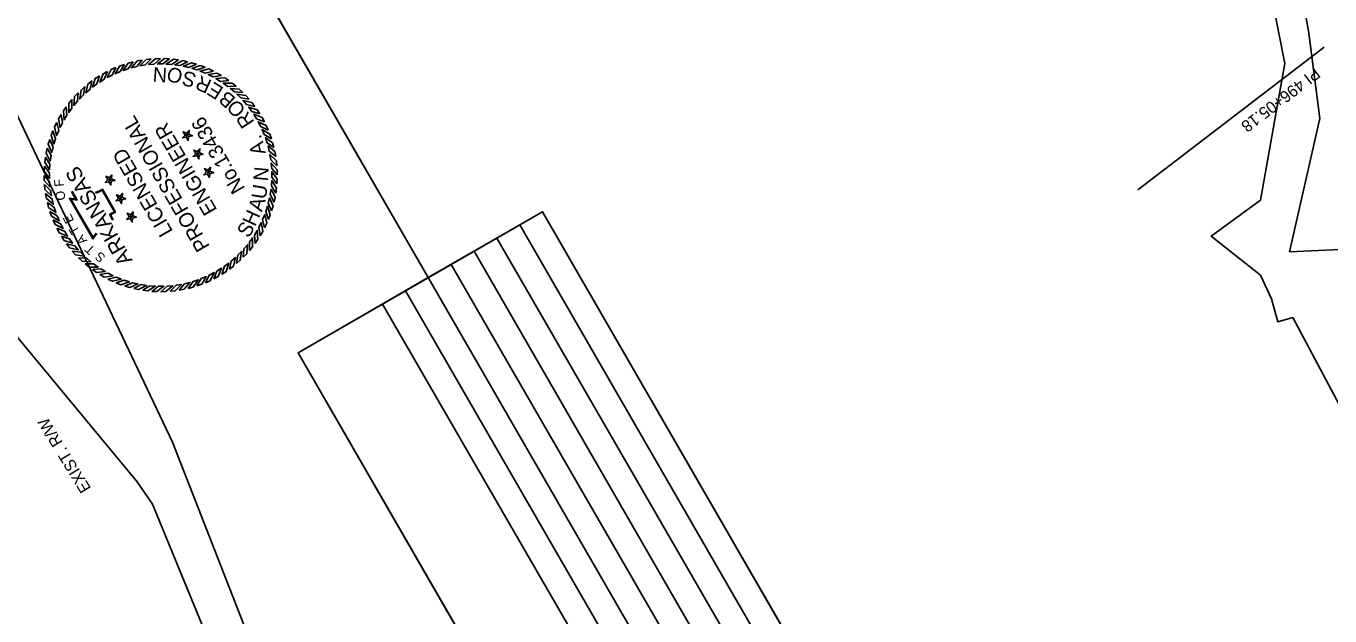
# Model space of a CAD drawing. Extents: x 956270 to 957915, y 1920520 to 1922423.
# Drawn here: x 956611 to 957278, y 1921729 to 1922031 of the extents above; entities that cross this region are included whole.
import ezdxf

# ---------------------------------------------------------------- set-up
doc = ezdxf.new("R2010")
doc.units = 0
for name, color, linetype in [('1', 7, 'Continuous'), ('Default', 7, 'Continuous'), ('G-ANNO-SYMB', 7, 'Continuous'), ('NO PLOT', 7, 'Continuous'), ('R_Draft', 7, 'Continuous'), ('R_Horz Alg Annot', 7, 'Continuous')]:
    doc.layers.add(name, color=color, linetype=linetype)

msp = doc.modelspace()

# ---------------------------------------------------------------- linework, layer by layer
at = {"layer": '1'}
msp.add_line((956816.66, 1921901.98), (956666.17, 1922162.65), dxfattribs=at)
at = {"layer": 'Default'}
for p, q in [((956749.98, 1921863.48), (956875.12, 1921935.73)), ((957087.62, 1921567.67), (956875.12, 1921935.73)), ((957075.93, 1921560.92), (956863.43, 1921928.98)), ((957064.24, 1921554.17), (956851.74, 1921922.23)), ((957052.55, 1921547.42), (956840.05, 1921915.48)), ((957040.85, 1921540.67), (956828.35, 1921908.73)), ((957040.85, 1921540.67), (956828.35, 1921908.73)), ((957029.16, 1921533.92), (956816.66, 1921901.98)), ((957017.47, 1921527.17), (956804.97, 1921895.23)), ((957005.78, 1921520.42), (956793.28, 1921888.48)), ((956962.48, 1921495.42), (956749.98, 1921863.48))]:
    msp.add_line(p, q, dxfattribs=at)
at = {"layer": 'G-ANNO-SYMB'}
for points in [[(956670.21, 1922013.36), (956667.68, 1922012.9), (956664.74, 1922009.4), (956667.43, 1922010.06)], [(956674.86, 1922013.92), (956672.3, 1922013.66), (956669.1, 1922010.4), (956671.83, 1922010.85)], [(956679.54, 1922014.12), (956676.97, 1922014.06), (956673.52, 1922011.06), (956676.28, 1922011.29)], [(956684.22, 1922013.95), (956681.66, 1922014.09), (956677.98, 1922011.37), (956680.75, 1922011.38)], [(956688.87, 1922013.41), (956686.33, 1922013.75), (956682.45, 1922011.32), (956685.21, 1922011.12)], [(956693.47, 1922012.5), (956690.96, 1922013.04), (956686.9, 1922010.93), (956689.64, 1922010.51)], [(956652.47, 1922007.55), (956650.21, 1922006.33), (956648.5, 1922002.09), (956650.85, 1922003.55)], [(956656.72, 1922009.52), (956654.37, 1922008.48), (956652.33, 1922004.39), (956654.79, 1922005.66)], [(956661.11, 1922011.15), (956658.69, 1922010.3), (956656.33, 1922006.38), (956658.89, 1922007.46)], [(956665.61, 1922012.44), (956663.13, 1922011.78), (956660.48, 1922008.06), (956663.11, 1922008.93)], [(956697.98, 1922011.24), (956695.52, 1922011.98), (956691.31, 1922010.19), (956694.01, 1922009.56)], [(956702.38, 1922009.63), (956699.98, 1922010.56), (956695.65, 1922009.11), (956698.29, 1922008.26)], [(956706.64, 1922007.68), (956704.32, 1922008.79), (956699.89, 1922007.68), (956702.45, 1922006.64)], [(956710.73, 1922005.4), (956708.51, 1922006.69), (956704, 1922005.94), (956706.48, 1922004.69)], [(956640.83, 1921999.73), (956638.91, 1921998.02), (956638.24, 1921993.5), (956640.19, 1921995.47)], [(956644.5, 1922002.64), (956642.46, 1922001.08), (956641.43, 1921996.63), (956643.53, 1921998.44)], [(956648.39, 1922005.25), (956646.23, 1922003.86), (956644.86, 1921999.5), (956647.09, 1922001.14)], [(956714.63, 1922002.81), (956712.52, 1922004.27), (956707.96, 1922003.87), (956710.34, 1922002.43)], [(956718.32, 1921999.92), (956716.33, 1922001.54), (956711.75, 1922001.5), (956714, 1921999.88)], [(956634.22, 1921993.1), (956632.6, 1921991.11), (956632.64, 1921986.53), (956634.26, 1921988.78)], [(956637.39, 1921996.54), (956635.62, 1921994.69), (956635.3, 1921990.12), (956637.09, 1921992.24)], [(956721.76, 1921996.75), (956719.91, 1921998.52), (956715.35, 1921998.84), (956717.46, 1921997.05)], [(956724.95, 1921993.31), (956723.24, 1921995.22), (956718.72, 1921995.9), (956720.69, 1921993.95)], [(956727.86, 1921989.64), (956726.3, 1921991.68), (956721.85, 1921992.71), (956723.66, 1921990.61)], [(956631.33, 1921989.41), (956629.87, 1921987.3), (956630.27, 1921982.74), (956631.71, 1921985.11)], [(956730.47, 1921985.75), (956729.08, 1921987.91), (956724.72, 1921989.28), (956726.36, 1921987.05)], [(956626.46, 1921981.42), (956625.35, 1921979.1), (956626.45, 1921974.67), (956627.5, 1921977.23)], [(956628.74, 1921985.51), (956627.45, 1921983.29), (956628.2, 1921978.78), (956629.45, 1921981.26)], [(956732.77, 1921981.67), (956731.55, 1921983.93), (956727.31, 1921985.64), (956728.77, 1921983.29)], [(956734.74, 1921977.42), (956733.7, 1921979.77), (956729.61, 1921981.81), (956730.88, 1921979.35)], [(956622.9, 1921972.76), (956622.16, 1921970.3), (956623.95, 1921966.09), (956624.58, 1921968.79)], [(956624.51, 1921977.16), (956623.58, 1921974.76), (956625.03, 1921970.43), (956625.87, 1921973.07)], [(956693.21, 1921974.87), (956692.18, 1921974.98), (956690.85, 1921973.51), (956692.79, 1921973.92)], [(956693.21, 1921974.87), (956693, 1921975.89), (956691.19, 1921976.69), (956692.18, 1921974.98)], [(956693.21, 1921974.87), (956692.79, 1921973.92), (956693.78, 1921972.2), (956693.99, 1921974.17)], [(956693.21, 1921974.87), (956694.12, 1921975.39), (956694.32, 1921977.36), (956693, 1921975.89)], [(956693.21, 1921974.87), (956693.99, 1921974.17), (956695.93, 1921974.58), (956694.12, 1921975.39)], [(956736.37, 1921973.03), (956735.52, 1921975.45), (956731.6, 1921977.81), (956732.68, 1921975.25)], [(956737.66, 1921968.53), (956737, 1921971.01), (956733.28, 1921973.66), (956734.15, 1921971.03)], [(956621.64, 1921968.25), (956621.1, 1921965.74), (956623.21, 1921961.68), (956623.63, 1921964.42)], [(956698.67, 1921965.42), (956698.45, 1921966.44), (956696.64, 1921967.25), (956697.63, 1921965.53)], [(956698.67, 1921965.42), (956699.57, 1921965.94), (956699.78, 1921967.91), (956698.45, 1921966.44)], [(956698.67, 1921965.42), (956699.44, 1921964.72), (956701.38, 1921965.14), (956699.57, 1921965.94)], [(956738.58, 1921963.93), (956738.12, 1921966.46), (956734.62, 1921969.4), (956735.28, 1921966.7)], [(956620.73, 1921963.65), (956620.39, 1921961.11), (956622.81, 1921957.23), (956623.02, 1921959.99)], [(956698.67, 1921965.42), (956697.63, 1921965.53), (956696.31, 1921964.06), (956698.24, 1921964.47)], [(956698.67, 1921965.42), (956698.24, 1921964.47), (956699.23, 1921962.75), (956699.44, 1921964.72)], [(956739.14, 1921959.28), (956738.88, 1921961.84), (956735.62, 1921965.04), (956736.07, 1921962.3)], [(956739.34, 1921954.6), (956739.28, 1921957.17), (956736.28, 1921960.62), (956736.51, 1921957.86)], [(956620.02, 1921954.32), (956620.08, 1921951.75), (956623.08, 1921948.3), (956622.85, 1921951.06)], [(956620.19, 1921959), (956620.05, 1921956.44), (956622.77, 1921952.76), (956622.76, 1921955.53)], [(956653.65, 1921952.03), (956653.43, 1921953.05), (956651.62, 1921953.85), (956652.62, 1921952.14)], [(956653.65, 1921952.03), (956654.55, 1921952.55), (956654.76, 1921954.52), (956653.43, 1921953.05)], [(956653.65, 1921952.03), (956654.43, 1921951.33), (956656.36, 1921951.74), (956654.55, 1921952.55)], [(956704.12, 1921955.97), (956703.09, 1921956.08), (956701.76, 1921954.61), (956703.7, 1921955.02)], [(956704.12, 1921955.97), (956703.91, 1921956.99), (956702.1, 1921957.8), (956703.09, 1921956.08)], [(956704.12, 1921955.97), (956703.7, 1921955.02), (956704.69, 1921953.31), (956704.9, 1921955.28)], [(956704.12, 1921955.97), (956705.02, 1921956.5), (956705.23, 1921958.47), (956703.91, 1921956.99)], [(956704.12, 1921955.97), (956704.9, 1921955.28), (956706.83, 1921955.69), (956705.02, 1921956.5)], [(956739.17, 1921949.92), (956739.31, 1921952.48), (956736.59, 1921956.16), (956736.6, 1921953.39)], [(956620.22, 1921949.64), (956620.48, 1921947.08), (956623.74, 1921943.88), (956623.29, 1921946.61)], [(956653.65, 1921952.03), (956652.62, 1921952.14), (956651.29, 1921950.66), (956653.23, 1921951.08)], [(956653.65, 1921952.03), (956653.23, 1921951.08), (956654.22, 1921949.36), (956654.43, 1921951.33)], [(956737.72, 1921940.67), (956738.26, 1921943.18), (956736.15, 1921947.24), (956735.73, 1921944.5)], [(956738.63, 1921945.27), (956738.97, 1921947.81), (956736.54, 1921951.69), (956736.34, 1921948.92)], [(956620.78, 1921944.98), (956621.24, 1921942.46), (956624.74, 1921939.52), (956624.08, 1921942.21)], [(956621.7, 1921940.39), (956622.36, 1921937.91), (956626.08, 1921935.26), (956625.21, 1921937.89)], [(956659.11, 1921942.58), (956658.07, 1921942.69), (956656.74, 1921941.22), (956658.68, 1921941.63)], [(956659.11, 1921942.58), (956658.89, 1921943.6), (956657.08, 1921944.41), (956658.07, 1921942.69)], [(956659.11, 1921942.58), (956658.68, 1921941.63), (956659.67, 1921939.91), (956659.88, 1921941.88)], [(956659.11, 1921942.58), (956660.01, 1921943.1), (956660.22, 1921945.07), (956658.89, 1921943.6)], [(956659.11, 1921942.58), (956659.88, 1921941.88), (956661.82, 1921942.3), (956660.01, 1921943.1)], [(956736.46, 1921936.16), (956737.2, 1921938.62), (956735.41, 1921942.83), (956734.78, 1921940.13)], [(956622.98, 1921935.89), (956623.84, 1921933.47), (956627.76, 1921931.11), (956626.68, 1921933.67)], [(956664.56, 1921933.13), (956663.52, 1921933.24), (956662.2, 1921931.77), (956664.14, 1921932.18)], [(956664.56, 1921933.13), (956664.34, 1921934.15), (956662.53, 1921934.96), (956663.52, 1921933.24)], [(956664.56, 1921933.13), (956664.14, 1921932.18), (956665.13, 1921930.47), (956665.33, 1921932.44)], [(956664.56, 1921933.13), (956665.46, 1921933.65), (956665.67, 1921935.62), (956664.34, 1921934.15)], [(956664.56, 1921933.13), (956665.33, 1921932.44), (956667.27, 1921932.85), (956665.46, 1921933.65)], [(956732.9, 1921927.5), (956734.01, 1921929.82), (956732.91, 1921934.25), (956731.86, 1921931.69)], [(956734.85, 1921931.76), (956735.78, 1921934.15), (956734.33, 1921938.49), (956733.48, 1921935.85)], [(956624.62, 1921931.5), (956625.65, 1921929.15), (956629.75, 1921927.11), (956628.48, 1921929.57)], [(956626.59, 1921927.25), (956627.81, 1921924.99), (956632.05, 1921923.28), (956630.59, 1921925.63)], [(956728.03, 1921919.51), (956729.49, 1921921.62), (956729.09, 1921926.17), (956727.65, 1921923.8)], [(956730.62, 1921923.41), (956731.91, 1921925.63), (956731.16, 1921930.14), (956729.91, 1921927.66)], [(956628.89, 1921923.17), (956630.28, 1921921.01), (956634.64, 1921919.64), (956633, 1921921.87)], [(956631.5, 1921919.28), (956633.06, 1921917.24), (956637.51, 1921916.21), (956635.7, 1921918.31)], [(956725.14, 1921915.82), (956726.76, 1921917.81), (956726.72, 1921922.39), (956725.1, 1921920.13)], [(956634.41, 1921915.6), (956636.12, 1921913.69), (956640.64, 1921913.02), (956638.67, 1921914.97)], [(956718.53, 1921909.19), (956720.44, 1921910.9), (956721.12, 1921915.42), (956719.17, 1921913.45)], [(956721.97, 1921912.38), (956723.74, 1921914.23), (956724.06, 1921918.79), (956722.27, 1921916.68)], [(956637.6, 1921912.17), (956639.45, 1921910.4), (956644.01, 1921910.08), (956641.9, 1921911.87)], [(956641.04, 1921909), (956643.03, 1921907.38), (956647.61, 1921907.42), (956645.35, 1921909.04)], [(956644.73, 1921906.11), (956646.84, 1921904.65), (956651.4, 1921905.05), (956649.02, 1921906.49)], [(956706.89, 1921901.37), (956709.15, 1921902.59), (956710.86, 1921906.83), (956708.51, 1921905.37)], [(956710.97, 1921903.67), (956713.13, 1921905.06), (956714.5, 1921909.42), (956712.27, 1921907.78)], [(956714.86, 1921906.28), (956716.9, 1921907.84), (956717.93, 1921912.29), (956715.83, 1921910.48)], [(956648.63, 1921903.52), (956650.85, 1921902.23), (956655.36, 1921902.98), (956652.88, 1921904.23)], [(956652.72, 1921901.24), (956655.04, 1921900.13), (956659.47, 1921901.23), (956656.91, 1921902.28)], [(956656.98, 1921899.29), (956659.37, 1921898.36), (956663.71, 1921899.81), (956661.07, 1921900.65)], [(956661.38, 1921897.68), (956663.84, 1921896.94), (956668.05, 1921898.73), (956665.35, 1921899.36)], [(956689.15, 1921895.56), (956691.68, 1921896.02), (956694.62, 1921899.52), (956691.93, 1921898.86)], [(956693.75, 1921896.48), (956696.23, 1921897.14), (956698.88, 1921900.86), (956696.25, 1921899.99)], [(956698.25, 1921897.76), (956700.67, 1921898.62), (956703.03, 1921902.53), (956700.47, 1921901.46)], [(956702.64, 1921899.4), (956704.99, 1921900.43), (956707.03, 1921904.53), (956704.57, 1921903.25)], [(956665.89, 1921896.41), (956668.4, 1921895.88), (956672.46, 1921897.99), (956669.72, 1921898.41)], [(956670.49, 1921895.51), (956673.03, 1921895.17), (956676.91, 1921897.59), (956674.14, 1921897.8)], [(956675.14, 1921894.97), (956677.7, 1921894.83), (956681.38, 1921897.55), (956678.61, 1921897.54)], [(956679.82, 1921894.8), (956682.39, 1921894.86), (956685.84, 1921897.86), (956683.08, 1921897.63)], [(956684.5, 1921895), (956687.06, 1921895.26), (956690.26, 1921898.52), (956687.53, 1921898.07)]]:
    msp.add_lwpolyline(points, close=True, dxfattribs=at)
for points in [[(956646.96, 1921924.53), (956645.05, 1921921.82), (956633, 1921942.65), (956636.2, 1921942.18), (956635.36, 1921943.58), (956634.66, 1921944.76), (956634.11, 1921946.01)], [(956646.65, 1921924.75), (956645.08, 1921922.53), (956633.73, 1921942.16), (956636.93, 1921941.68), (956635.69, 1921943.78), (956635, 1921944.93), (956634.46, 1921946.16)], [(956646.12, 1921945.57), (956646.73, 1921945.34), (956647.37, 1921945.51), (956648.57, 1921946.03), (956649.7, 1921946.69), (956656.03, 1921935.71), (956654.42, 1921934.78), (956653.74, 1921934.39), (956653.95, 1921933.5), (956654.83, 1921931.98), (956654.64, 1921931.61)], [(956646.25, 1921945.93), (956646.75, 1921945.74), (956647.25, 1921945.87), (956648.4, 1921946.37), (956649.84, 1921947.21), (956656.55, 1921935.57), (956654.61, 1921934.45), (956654.18, 1921934.2), (956654.3, 1921933.65), (956655.26, 1921931.99), (956654.98, 1921931.44)]]:
    msp.add_lwpolyline(points, dxfattribs=at)
at = {"layer": 'NO PLOT'}
for points in [[(957915.18, 1921041.6), (957117.5, 1922423.23), (956666.17, 1922162.65), (956816.66, 1921901.98), (956875.12, 1921935.73), (957087.62, 1921567.67), (957029.16, 1921533.92), (957172.25, 1921286.08), (957225.74, 1921316.96), (957397.07, 1921020.21), (957343.58, 1920989.33), (957463.85, 1920781.02)], [(957915.18, 1921041.6), (957117.5, 1922423.23), (956666.17, 1922162.65), (956816.66, 1921901.98), (956875.12, 1921935.73), (957087.62, 1921567.67), (957029.16, 1921533.92), (957172.25, 1921286.08), (957225.74, 1921316.96), (957397.07, 1921020.21), (957343.58, 1920989.33), (957463.85, 1920781.02)], [(957915.18, 1921041.6), (957117.5, 1922423.23), (956666.17, 1922162.65), (956816.66, 1921901.98), (956875.12, 1921935.73), (957087.62, 1921567.67), (957029.16, 1921533.92), (957172.25, 1921286.08), (957225.74, 1921316.96), (957397.07, 1921020.21), (957343.58, 1920989.33), (957463.85, 1920781.02)], [(957012.51, 1920520.44), (956420.48, 1921545.87), (956463.26, 1921570.57), (956365.36, 1921740.14), (956378, 1921747.44), (956270.25, 1921934.07), (956666.17, 1922162.65), (956816.66, 1921901.98), (956749.98, 1921863.48), (956962.48, 1921495.42), (957029.16, 1921533.92), (957172.25, 1921286.08), (957120.9, 1921256.43), (957292.23, 1920959.68), (957343.58, 1920989.33), (957463.85, 1920781.02)], [(957012.51, 1920520.44), (956420.48, 1921545.87), (956463.26, 1921570.57), (956365.36, 1921740.14), (956378, 1921747.44), (956270.25, 1921934.07), (956666.17, 1922162.65), (956816.66, 1921901.98), (956749.98, 1921863.48), (956962.48, 1921495.42), (957029.16, 1921533.92), (957172.25, 1921286.08), (957120.9, 1921256.43), (957292.23, 1920959.68), (957343.58, 1920989.33), (957463.85, 1920781.02)], [(957012.51, 1920520.44), (956420.48, 1921545.87), (956463.26, 1921570.57), (956365.36, 1921740.14), (956378, 1921747.44), (956270.25, 1921934.07), (956666.17, 1922162.65), (956816.66, 1921901.98), (956749.98, 1921863.48), (956962.48, 1921495.42), (957029.16, 1921533.92), (957172.25, 1921286.08), (957120.9, 1921256.43), (957292.23, 1920959.68), (957343.58, 1920989.33), (957463.85, 1920781.02)]]:
    msp.add_lwpolyline(points, close=True, dxfattribs=at)
for points in [[(957342.58, 1921919.03), (957257.4, 1921915.24), (957272.85, 1921983.36), (957267.37, 1922027.06), (957246.99, 1922143.57)], [(957240.29, 1922085.93), (957255.08, 1922011.58), (957242.6, 1921941.72), (957217.28, 1921923.16), (957242.63, 1921903.32), (957248.1, 1921891.14), (957251.36, 1921879.39), (957259.14, 1921881.52), (957406.57, 1921604.71)], [(956978.43, 1921300.96), (956891.96, 1921416.34), (956761.21, 1921624.84), (956685.68, 1921817.75), (956598.64, 1922001.42), (956569.16, 1922006.84), (956549.42, 1922003.64), (956496.56, 1922078), (956484.6, 1922065.05), (956487.74, 1922034.93), (956520.15, 1921988.76), (956538.43, 1921986.13), (956552.84, 1921975.42), (956577.89, 1921905.71), (956667.63, 1921797.4), (956675.52, 1921785.98), (956734.33, 1921642.98), (956883.87, 1921386.21), (956963.43, 1921282.81)]]:
    msp.add_lwpolyline(points, dxfattribs=at)
at = {"layer": 'R_Horz Alg Annot'}
msp.add_lwpolyline([(957179.79, 1921946.96), (957275.07, 1922019.91)], dxfattribs=at)

# ---------------------------------------------------------------- texts
at = {"layer": 'G-ANNO-SYMB'}
for s, height, rotation, p in [('N', 7.5, 176.10067, (956683.17, 1922009.29)), ('O', 7.5, 164.77573, (956691.62, 1922008.15)), ('S', 7.5, 163.48784, (956698.5, 1922006.18)), ('R', 7.5, 155.65967, (956706.37, 1922002.76)), ('E', 7.5, 147.83149, (956712.41, 1921998.93)), ('B', 7.5, 138.88501, (956718.55, 1921993.72)), ('O', 7.5, 131.42961, (956723.68, 1921988.01)), ('R', 7.5, 123.22866, (956727.94, 1921981.6)), ('PROFESSIONAL', 7.5, 120, (956705.07, 1921917.98)), ('ENGINEER', 7.5, 120, (956708.79, 1921936.62)), ('No.13436', 7.47, 120, (956723.09, 1921947.61)), ('.', 7.5, 111.30002, (956731.72, 1921973.16)), ('LICENSED', 7.5, 120, (956686.17, 1921925.63)), ('A', 7.5, 103.09908, (956733.51, 1921965.69)), ('ARKANSAS', 7.747, 120, (956665.47, 1921910.9)), ('N', 7.5, 84.93262, (956734.47, 1921951.15)), ('F', 4.75, 95.36282, (956630.13, 1921948.76)), ('O', 4.75, 101.2218, (956631.16, 1921941.96)), ('U', 7.5, 80.90262, (956733.42, 1921941.81)), ('A', 7.5, 73.44722, (956731.52, 1921935.32)), ('E', 4.75, 116.67203, (956635.51, 1921931.17)), ('H', 7.5, 65.61905, (956727.97, 1921927.77)), ('T', 4.75, 121.47887, (956638.43, 1921925.84)), ('S', 7.5, 58.16364, (956724.59, 1921921.87)), ('A', 4.75, 128.67877, (956642.31, 1921921)), ('T', 4.75, 136.90148, (956646.49, 1921916.76)), ('S', 4.75, 139.77256, (956651.86, 1921912.89))]:
    msp.add_text(s, height=height, rotation=rotation, dxfattribs=at).set_placement(p)
at = {"layer": 'R_Draft'}
msp.add_text('EXIST. R/W', height=6, rotation=121.48809, dxfattribs=at).set_placement((956644.21, 1921794.11))
at = {"layer": 'R_Horz Alg Annot'}
msp.add_text('PI 496+05.18', height=6, rotation=217.43909, dxfattribs=at).set_placement((957270.17, 1922009.86))

doc.saveas('drawing.dxf')
